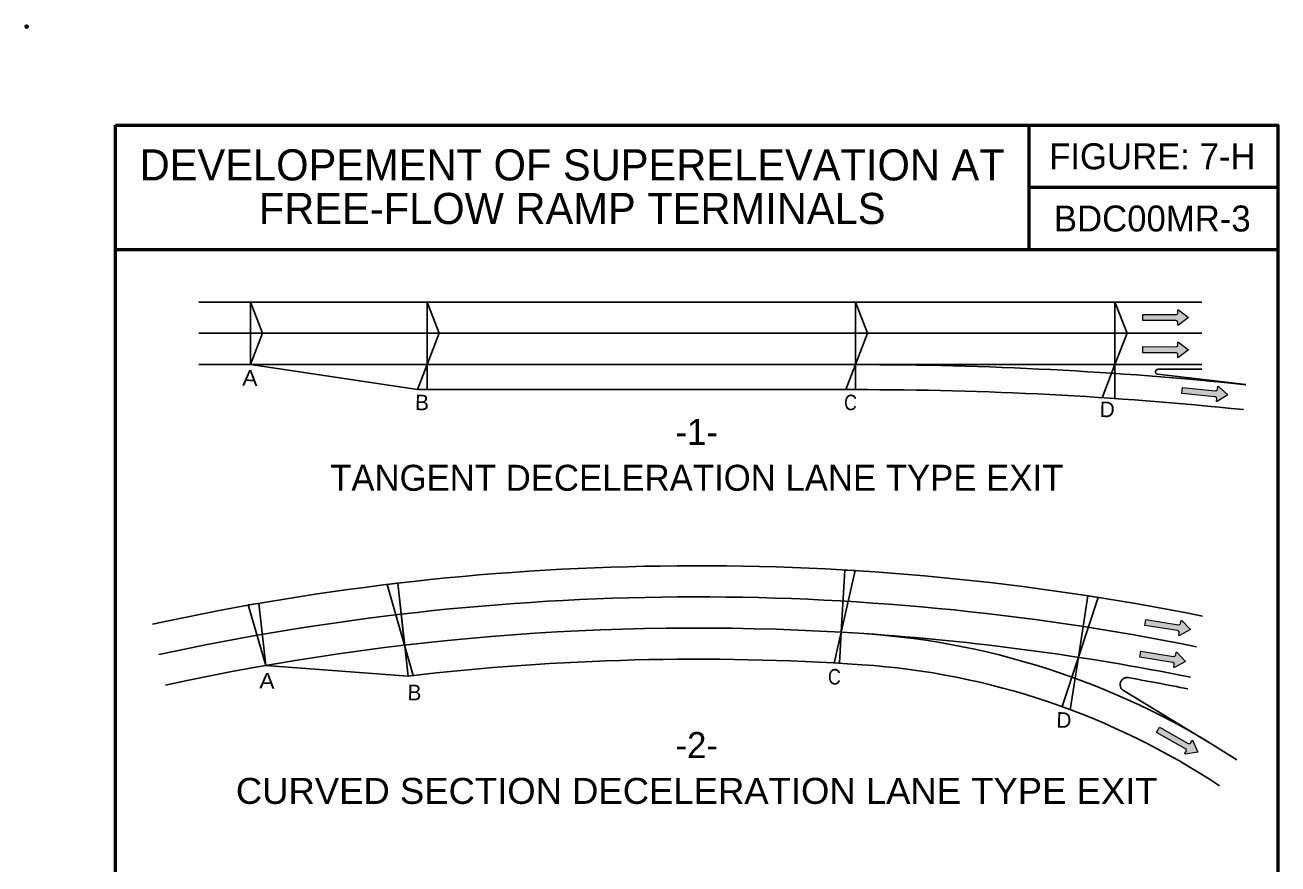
# Model space of a CAD drawing. Extents: x 0.641 to 1.316, y 2.867 to 3.751.
# Drawn here: x 0.641 to 1.27, y 3.331 to 3.751 of the extents above; entities that cross this region are included whole.
import ezdxf
from ezdxf.enums import TextEntityAlignment as Align

# ---------------------------------------------------------------- set-up
doc = ezdxf.new("R2010")
doc.units = 0
doc.header["$LTSCALE"] = 0.0031
doc.header["$PDMODE"] = 32
doc.header["$PDSIZE"] = 0.00155
doc.linetypes.add('DASH_DOUBLE_DOT', pattern=[9.2, 5, -1.2, 0.3, -1.2, 0.3, -1.2])
doc.linetypes.add('LONG_DASHED', pattern=[7.5, 6, -1.5])
doc.layers.add('1', color=7, linetype='Continuous', lineweight=25)
doc.layers.add('60', color=7, linetype='DASH_DOUBLE_DOT', lineweight=13)

msp = doc.modelspace()

# ---------------------------------------------------------------- hatches: boundary and pattern name
at = {"layer": '60'}
for points in [[(1.218483, 3.606142), (1.218808, 3.606258), (1.219133, 3.606392), (1.219325, 3.606525), (1.219467, 3.606825), (1.219492, 3.60715), (1.219492, 3.608325), (1.219575, 3.608458), (1.219683, 3.608508), (1.219792, 3.608508), (1.219817, 3.608483), (1.224875, 3.60465), (1.219792, 3.600817), (1.219683, 3.600792), (1.219542, 3.600792), (1.219492, 3.600867), (1.219433, 3.601033), (1.219467, 3.600975), (1.219492, 3.602125), (1.219433, 3.60245), (1.219358, 3.602583), (1.2193, 3.602692), (1.219275, 3.6028), (1.219083, 3.602933), (1.218917, 3.603042), (1.218808, 3.6031), (1.218483, 3.603125), (1.201867, 3.603183), (1.201867, 3.6062)], [(1.218483, 3.590008), (1.218808, 3.590125), (1.219133, 3.590258), (1.219325, 3.590392), (1.219467, 3.590692), (1.219492, 3.591017), (1.219492, 3.592192), (1.219575, 3.592325), (1.219683, 3.592375), (1.219792, 3.592375), (1.219817, 3.59235), (1.224875, 3.588517), (1.219792, 3.584683), (1.219683, 3.584658), (1.219542, 3.584658), (1.219492, 3.584733), (1.219433, 3.5849), (1.219467, 3.584842), (1.219492, 3.585992), (1.219433, 3.586317), (1.219358, 3.58645), (1.2193, 3.586558), (1.219275, 3.586667), (1.219083, 3.5868), (1.218917, 3.586908), (1.218808, 3.586967), (1.218483, 3.586992), (1.201867, 3.58705), (1.201867, 3.590067)], [(1.2384, 3.567958), (1.238733, 3.568042), (1.239075, 3.568142), (1.239275, 3.568258), (1.23945, 3.568542), (1.2395, 3.568867), (1.239617, 3.570033), (1.239717, 3.570158), (1.239825, 3.5702), (1.239933, 3.570183), (1.239958, 3.570158), (1.244617, 3.56585), (1.239183, 3.562533), (1.239075, 3.562517), (1.238933, 3.562533), (1.238892, 3.562608), (1.23885, 3.562783), (1.238875, 3.562725), (1.239008, 3.563867), (1.238983, 3.564192), (1.238925, 3.564333), (1.238875, 3.56445), (1.238867, 3.564558), (1.238683, 3.564708), (1.238533, 3.564833), (1.238425, 3.5649), (1.238108, 3.564958), (1.221575, 3.566642), (1.221867, 3.569642)], [(1.219783, 3.450575), (1.220125, 3.450642), (1.220467, 3.450725), (1.220675, 3.450825), (1.220858, 3.451092), (1.220933, 3.451408), (1.221117, 3.452575), (1.221217, 3.452692), (1.221333, 3.452725), (1.221442, 3.452708), (1.221458, 3.452675), (1.225875, 3.448125), (1.220275, 3.445108), (1.220158, 3.445092), (1.220017, 3.445125), (1.219975, 3.445208), (1.219942, 3.445375), (1.219967, 3.445308), (1.220167, 3.446442), (1.220158, 3.446775), (1.220108, 3.446925), (1.220067, 3.447042), (1.220058, 3.447142), (1.219892, 3.447308), (1.219742, 3.447442), (1.21965, 3.447508), (1.219325, 3.447592), (1.202908, 3.450175), (1.203375, 3.453158)], [(1.217325, 3.434625), (1.217667, 3.434692), (1.218008, 3.434775), (1.218225, 3.434875), (1.2184, 3.435158), (1.218475, 3.435475), (1.21865, 3.436625), (1.218758, 3.436742), (1.218875, 3.436775), (1.218975, 3.436758), (1.219, 3.436742), (1.223425, 3.432175), (1.217817, 3.429158), (1.217692, 3.429158), (1.21755, 3.429175), (1.217517, 3.429258), (1.217483, 3.429425), (1.217508, 3.429375), (1.217708, 3.430492), (1.2177, 3.430825), (1.217658, 3.430975), (1.217617, 3.431092), (1.2176, 3.431208), (1.217425, 3.431358), (1.217292, 3.431492), (1.217192, 3.431575), (1.216867, 3.431642), (1.20045, 3.434225), (1.200908, 3.437225)], [(1.224733, 3.390983), (1.225083, 3.390925), (1.22545, 3.390875), (1.225658, 3.3909), (1.225933, 3.391083), (1.226117, 3.391375), (1.226683, 3.392392), (1.226833, 3.392475), (1.22695, 3.392483), (1.227042, 3.392417), (1.22705, 3.392367), (1.2296, 3.386558), (1.2233, 3.385683), (1.223192, 3.385708), (1.223067, 3.3858), (1.223058, 3.385858), (1.223092, 3.38605), (1.2231, 3.386), (1.223667, 3.386983), (1.223775, 3.3873), (1.223783, 3.387442), (1.223767, 3.387575), (1.223817, 3.387667), (1.223708, 3.387883), (1.223617, 3.388058), (1.22355, 3.388167), (1.223283, 3.388342), (1.208792, 3.396483), (1.21025, 3.399108)]]:
    msp.add_hatch(color=256, dxfattribs=at).paths.add_polyline_path(points)

# ---------------------------------------------------------------- linework, layer by layer
at = {"layer": '1', "lineweight": 53}
for p, q in [((1.14475, 3.701267), (1.14475, 3.638767)), ((1.14475, 3.701267), (1.14475, 3.638767)), ((1.14475, 3.670017), (1.26975, 3.670017)), ((0.686417, 3.638767), (1.26975, 3.638767))]:
    msp.add_line(p, q, dxfattribs=at)
at = {"layer": '1'}
for p, q in [((0.728208, 3.612433), (1.231517, 3.612433)), ((0.728208, 3.596758), (1.231517, 3.596758)), ((0.754183, 3.581075), (0.837917, 3.568525)), ((0.84275, 3.581075), (0.837917, 3.568525)), ((0.84275, 3.581075), (0.84275, 3.568525)), ((1.057775, 3.581075), (1.052942, 3.568525)), ((1.057775, 3.581075), (1.057775, 3.568525)), ((1.187958, 3.581075), (1.181567, 3.564475)), ((1.187958, 3.581075), (1.187958, 3.564042)), ((0.837917, 3.568525), (1.057775, 3.568525)), ((0.835767, 3.425075), (0.822717, 3.470758)), ((0.828017, 3.471358), (0.833225, 3.424775)), ((1.050583, 3.446792), (1.04705, 3.431342)), ((1.049683, 3.431192), (1.050583, 3.446792)), ((1.1614, 3.40945), (1.1696, 3.4342)), ((1.1696, 3.4342), (1.16555, 3.407925)), ((0.833225, 3.424775), (0.761833, 3.430133))]:
    msp.add_line(p, q, dxfattribs=at)
at = {"layer": '1', "linetype": 'LONG_DASHED'}
for p, q in [((1.209542, 3.5787), (1.231517, 3.5787)), ((1.2094, 3.576267), (1.2537, 3.571125)), ((1.19225, 3.4175), (1.235433, 3.391358))]:
    msp.add_line(p, q, dxfattribs=at)
at = {"layer": '1', "lineweight": 53}
msp.add_lwpolyline([(0.686417, 3.701267), (1.26975, 3.701267), (1.26975, 2.9096), (0.686417, 2.9096)], close=True, dxfattribs=at)
at = {"layer": '1'}
for points in [[(0.754183, 3.581075), (0.754183, 3.612433), (0.760225, 3.596758)], [(0.84275, 3.581075), (0.84275, 3.612433), (0.8488, 3.596758)], [(1.057775, 3.581075), (1.057775, 3.612433), (1.063817, 3.596758)], [(1.187958, 3.581075), (1.187958, 3.612433), (1.194008, 3.596758)], [(1.052383, 3.477992), (1.050583, 3.446792), (1.057642, 3.477675)], [(0.822717, 3.470758), (0.831492, 3.4403), (0.828017, 3.471358)], [(1.174367, 3.465083), (1.1696, 3.4342), (1.179567, 3.464275)], [(0.753067, 3.460583), (0.761833, 3.430133), (0.758367, 3.461192)]]:
    msp.add_lwpolyline(points, close=True, dxfattribs=at)
msp.add_lwpolyline([(0.728208, 3.581075), (1.057775, 3.581075), (1.231517, 3.581075)], dxfattribs=at)
for centre, radius, start, end in [((1.057776, 1.675675), 1.905399, 84.09874, 90), ((1.057776, 1.675675), 1.892853, 84.09874, 90), ((0.978083, 2.192904), 1.287235, 78.62538, 102.25174), ((0.978083, 2.192904), 1.27161, 78.62538, 102.25174), ((0.978083, 2.192904), 1.255985, 86.17139, 102.25174), ((1.036268, 3.062345), 0.384599, 56.40894, 86.17139), ((0.978083, 2.192904), 1.255985, 78.62538, 86.17131), ((0.978083, 2.192904), 1.24036, 86.17139, 96.70679), ((1.036268, 3.062345), 0.368974, 56.40894, 86.17139)]:
    msp.add_arc(centre, radius, start, end, dxfattribs=at)
at = {"layer": '1', "linetype": 'LONG_DASHED'}
for centre, radius, start, end in [((1.209539, 3.57748), 0.001219, 90, 263.37736), ((1.194073, 3.420508), 0.003517, 80.02128, 238.81001), ((0.978083, 2.192904), 1.249978, 78.62538, 80.07993)]:
    msp.add_arc(centre, radius, start, end, dxfattribs=at)
at = {"layer": '1'}
msp.add_point((0.6418, 3.750658), dxfattribs=at)
at = {"layer": '60'}
for points in [[(1.218483, 3.606142), (1.218808, 3.606258), (1.219133, 3.606392), (1.219325, 3.606525), (1.219467, 3.606825), (1.219492, 3.60715), (1.219492, 3.608325), (1.219575, 3.608458), (1.219683, 3.608508), (1.219792, 3.608508), (1.219817, 3.608483), (1.224875, 3.60465), (1.219792, 3.600817), (1.219683, 3.600792), (1.219542, 3.600792), (1.219492, 3.600867), (1.219433, 3.601033), (1.219467, 3.600975), (1.219492, 3.602125), (1.219433, 3.60245), (1.219358, 3.602583), (1.2193, 3.602692), (1.219275, 3.6028), (1.219083, 3.602933), (1.218917, 3.603042), (1.218808, 3.6031), (1.218483, 3.603125), (1.201867, 3.603183), (1.201867, 3.6062)], [(1.218483, 3.590008), (1.218808, 3.590125), (1.219133, 3.590258), (1.219325, 3.590392), (1.219467, 3.590692), (1.219492, 3.591017), (1.219492, 3.592192), (1.219575, 3.592325), (1.219683, 3.592375), (1.219792, 3.592375), (1.219817, 3.59235), (1.224875, 3.588517), (1.219792, 3.584683), (1.219683, 3.584658), (1.219542, 3.584658), (1.219492, 3.584733), (1.219433, 3.5849), (1.219467, 3.584842), (1.219492, 3.585992), (1.219433, 3.586317), (1.219358, 3.58645), (1.2193, 3.586558), (1.219275, 3.586667), (1.219083, 3.5868), (1.218917, 3.586908), (1.218808, 3.586967), (1.218483, 3.586992), (1.201867, 3.58705), (1.201867, 3.590067)], [(1.2384, 3.567958), (1.238733, 3.568042), (1.239075, 3.568142), (1.239275, 3.568258), (1.23945, 3.568542), (1.2395, 3.568867), (1.239617, 3.570033), (1.239717, 3.570158), (1.239825, 3.5702), (1.239933, 3.570183), (1.239958, 3.570158), (1.244617, 3.56585), (1.239183, 3.562533), (1.239075, 3.562517), (1.238933, 3.562533), (1.238892, 3.562608), (1.23885, 3.562783), (1.238875, 3.562725), (1.239008, 3.563867), (1.238983, 3.564192), (1.238925, 3.564333), (1.238875, 3.56445), (1.238867, 3.564558), (1.238683, 3.564708), (1.238533, 3.564833), (1.238425, 3.5649), (1.238108, 3.564958), (1.221575, 3.566642), (1.221867, 3.569642)], [(1.219783, 3.450575), (1.220125, 3.450642), (1.220467, 3.450725), (1.220675, 3.450825), (1.220858, 3.451092), (1.220933, 3.451408), (1.221117, 3.452575), (1.221217, 3.452692), (1.221333, 3.452725), (1.221442, 3.452708), (1.221458, 3.452675), (1.225875, 3.448125), (1.220275, 3.445108), (1.220158, 3.445092), (1.220017, 3.445125), (1.219975, 3.445208), (1.219942, 3.445375), (1.219967, 3.445308), (1.220167, 3.446442), (1.220158, 3.446775), (1.220108, 3.446925), (1.220067, 3.447042), (1.220058, 3.447142), (1.219892, 3.447308), (1.219742, 3.447442), (1.21965, 3.447508), (1.219325, 3.447592), (1.202908, 3.450175), (1.203375, 3.453158)], [(1.217325, 3.434625), (1.217667, 3.434692), (1.218008, 3.434775), (1.218225, 3.434875), (1.2184, 3.435158), (1.218475, 3.435475), (1.21865, 3.436625), (1.218758, 3.436742), (1.218875, 3.436775), (1.218975, 3.436758), (1.219, 3.436742), (1.223425, 3.432175), (1.217817, 3.429158), (1.217692, 3.429158), (1.21755, 3.429175), (1.217517, 3.429258), (1.217483, 3.429425), (1.217508, 3.429375), (1.217708, 3.430492), (1.2177, 3.430825), (1.217658, 3.430975), (1.217617, 3.431092), (1.2176, 3.431208), (1.217425, 3.431358), (1.217292, 3.431492), (1.217192, 3.431575), (1.216867, 3.431642), (1.20045, 3.434225), (1.200908, 3.437225)], [(1.224733, 3.390983), (1.225083, 3.390925), (1.22545, 3.390875), (1.225658, 3.3909), (1.225933, 3.391083), (1.226117, 3.391375), (1.226683, 3.392392), (1.226833, 3.392475), (1.22695, 3.392483), (1.227042, 3.392417), (1.22705, 3.392367), (1.2296, 3.386558), (1.2233, 3.385683), (1.223192, 3.385708), (1.223067, 3.3858), (1.223058, 3.385858), (1.223092, 3.38605), (1.2231, 3.386), (1.223667, 3.386983), (1.223775, 3.3873), (1.223783, 3.387442), (1.223767, 3.387575), (1.223817, 3.387667), (1.223708, 3.387883), (1.223617, 3.388058), (1.22355, 3.388167), (1.223283, 3.388342), (1.208792, 3.396483), (1.21025, 3.399108)]]:
    msp.add_lwpolyline(points, close=True, dxfattribs=at)

# ---------------------------------------------------------------- texts
at = {"layer": '1'}
for s, height, p in [('FIGURE: 7-H', 0.01303, (1.206725, 3.679075)), ('DEVELOPEMENT OF SUPERELEVATION AT', 0.01562, (0.915587, 3.673475)), ('FREE-FLOW RAMP TERMINALS', 0.01562, (0.915583, 3.6516)), ('BDC00MR-3', 0.01303, (1.206692, 3.647858)), ('-1-', 0.01303, (0.978087, 3.540767)), ('TANGENT DECELERATION LANE TYPE EXIT', 0.01303, (0.978083, 3.517767)), ('-2-', 0.01303, (0.978087, 3.383658))]:
    msp.add_text(s, height=height, dxfattribs=at).set_placement(p, align=Align.CENTER)
for s, width, p in [('A', 1.1, (0.753804, 3.570473)), ('C', 0.85, (1.055163, 3.558165)), ('C', 0.85, (1.047083, 3.420532)), ('A', 1.1, (0.762379, 3.418531))]:
    msp.add_text(s, height=0.007817, rotation=358.596, dxfattribs=dict(at, width=width)).set_placement(p, align=Align.CENTER)
for s, p in [('B', (0.840138, 3.558168)), ('D', (1.183988, 3.554666)), ('B', (0.836354, 3.412643)), ('D', (1.162263, 3.398832))]:
    msp.add_text(s, height=0.007817, rotation=358.596, dxfattribs=at).set_placement(p, align=Align.CENTER)
at = {"layer": '1', "width": 1.05}
msp.add_text('CURVED SECTION DECELERATION LANE TYPE EXIT', height=0.01303, dxfattribs=at).set_placement((0.978083, 3.360658), align=Align.CENTER)

doc.saveas('drawing.dxf')
